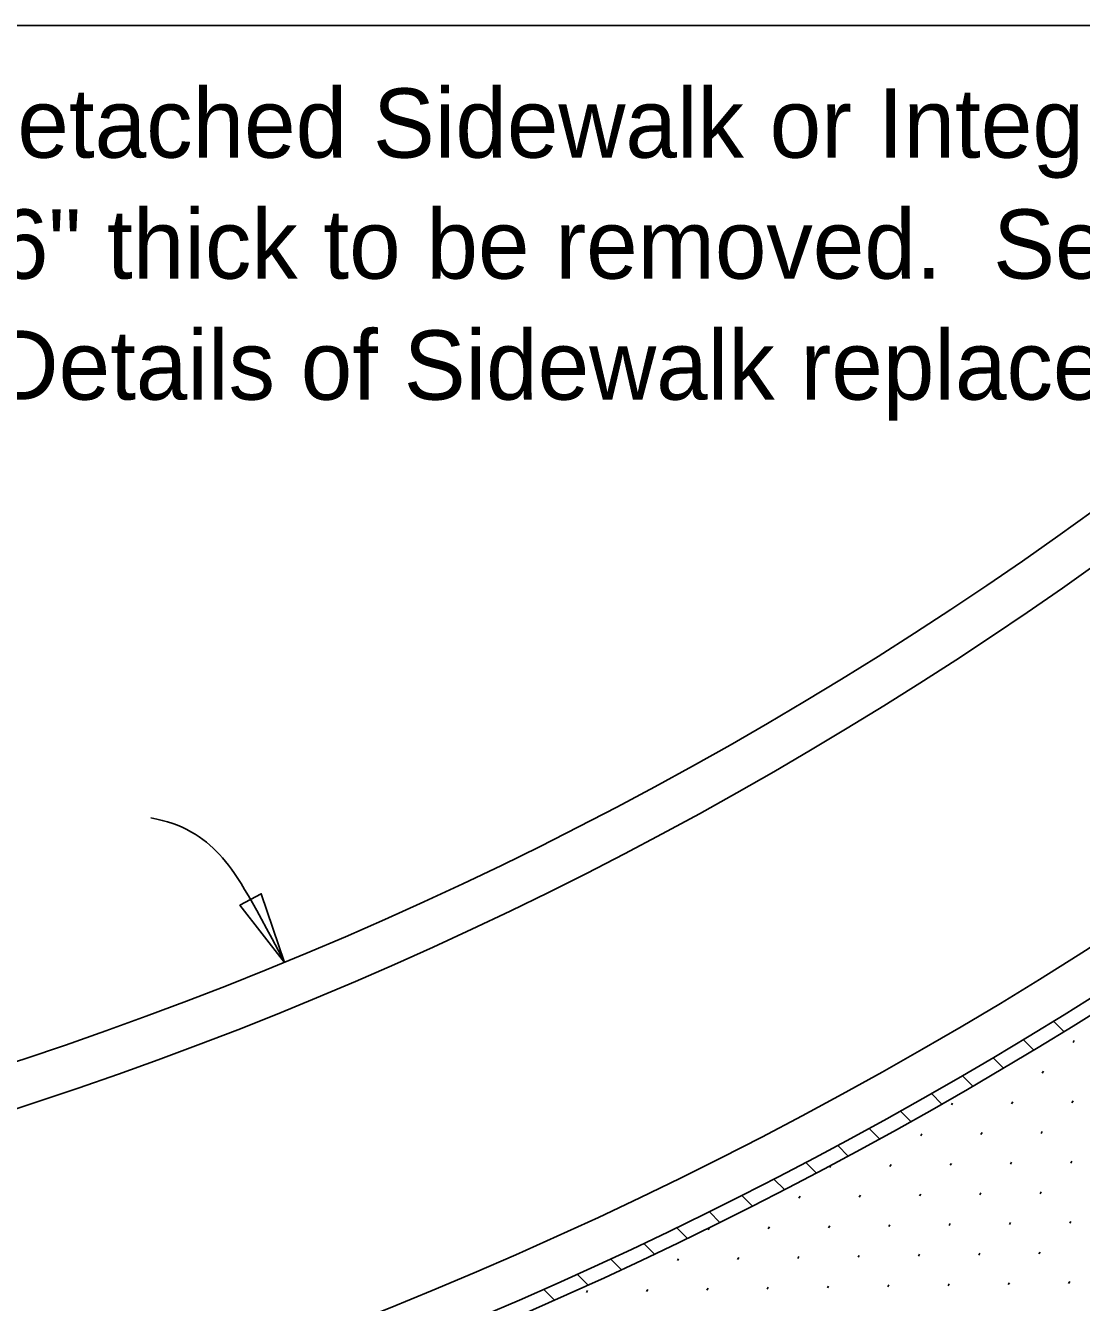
# Model space of a CAD drawing. Extents: x 0 to 41.1, y 0 to 25.9.
# Drawn here: x 31.762 to 34.833, y 22.231 to 25.946 of the extents above; entities that cross this region are included whole.
import ezdxf

# ---------------------------------------------------------------- set-up
doc = ezdxf.new("R2010")
doc.units = 0
for name, color, linetype in [('Dimension', 7, 'Continuous'), ('ExistSuperStruct', 7, 'Continuous'), ('Miscellaneous', 7, 'Continuous'), ('Miscellaneous1', 7, 'Continuous')]:
    doc.layers.add(name, color=color, linetype=linetype)

msp = doc.modelspace()

# ---------------------------------------------------------------- linework, layer by layer
at = {"layer": 'Dimension'}
for points in [[(0, 0), (41.0506, 0), (41.0506, 25.9461), (0, 25.9461)], [(32.5153, 23.2202), (32.4472, 23.4201), (32.3851, 23.3865)]]:
    msp.add_lwpolyline(points, close=True, dxfattribs=at)
msp.add_open_spline([(32.1263, 23.6406), (32.2187, 23.6248), (32.338, 23.5452), (32.4097, 23.4202), (32.5153, 23.2202)], degree=3, dxfattribs=at)
at = {"layer": 'ExistSuperStruct'}
for radius, start, end in [(11.3394, 267.40102, 307.93264), (11.4702, 267.84731, 307.49092), (12.3856, 268.00648, 307.27295), (12.5106, 272.22541, 307.24718), (12.5523, 272.40859, 307.2387)]:
    msp.add_arc((28.1995, 33.7062), radius, start, end, dxfattribs=at)
at = {"layer": 'Miscellaneous'}
for p, q in [((34.7522, 23.0488), (34.7821, 23.0189)), ((34.6643, 22.9953), (34.6945, 22.9651)), ((34.8084, 22.9871), (34.8117, 22.9927)), ((34.5758, 22.9424), (34.6059, 22.9123)), ((34.4867, 22.8901), (34.5169, 22.8599)), ((34.7191, 22.8979), (34.7224, 22.9035)), ((34.3969, 22.8384), (34.4272, 22.8082)), ((34.6299, 22.8086), (34.6331, 22.8142)), ((34.8052, 22.8118), (34.8084, 22.8174)), ((34.3065, 22.7874), (34.3368, 22.7571)), ((34.4546, 22.8054), (34.4578, 22.8109)), ((34.2155, 22.737), (34.246, 22.7065)), ((34.3653, 22.7161), (34.3685, 22.7217)), ((34.5406, 22.7193), (34.5438, 22.7249)), ((34.7159, 22.7226), (34.7191, 22.7282)), ((34.1239, 22.6872), (34.1543, 22.6568)), ((34.0316, 22.6381), (34.0623, 22.6073)), ((34.1007, 22.6236), (34.104, 22.6292)), ((34.276, 22.6268), (34.2793, 22.6324)), ((34.4513, 22.63), (34.4546, 22.6356)), ((34.6266, 22.6333), (34.6299, 22.6389)), ((34.8019, 22.6365), (34.8052, 22.6421)), ((33.9386, 22.5896), (33.9692, 22.5591)), ((34.7127, 22.5473), (34.7159, 22.5529)), ((33.845, 22.5418), (33.876, 22.5108)), ((34.0114, 22.5343), (34.0147, 22.5399)), ((34.1867, 22.5375), (34.19, 22.5431)), ((34.362, 22.5408), (34.3653, 22.5464)), ((34.5374, 22.544), (34.5406, 22.5496)), ((33.7508, 22.4946), (33.7815, 22.4639)), ((33.6559, 22.4481), (33.6869, 22.417)), ((33.7469, 22.4418), (33.7501, 22.4474)), ((33.9222, 22.445), (33.9254, 22.4506)), ((34.0975, 22.4483), (34.1007, 22.4539)), ((34.2728, 22.4515), (34.276, 22.4571)), ((34.4481, 22.4547), (34.4513, 22.4603)), ((34.6234, 22.458), (34.6266, 22.4636)), ((34.7987, 22.4612), (34.8019, 22.4668)), ((33.5603, 22.4023), (33.5912, 22.3714)), ((34.1835, 22.3622), (34.1867, 22.3678)), ((34.3588, 22.3655), (34.362, 22.3711)), ((34.5341, 22.3687), (34.5374, 22.3743)), ((34.7094, 22.372), (34.7127, 22.3776)), ((33.464, 22.3571), (33.4952, 22.326)), ((33.6576, 22.3525), (33.6608, 22.3581)), ((33.8329, 22.3557), (33.8361, 22.3613)), ((34.0082, 22.359), (34.0114, 22.3646)), ((33.3671, 22.3126), (33.3982, 22.2815)), ((33.2694, 22.2689), (33.3007, 22.2376)), ((33.393, 22.26), (33.3963, 22.2656)), ((33.5683, 22.2632), (33.5716, 22.2688)), ((33.7436, 22.2665), (33.7469, 22.2721)), ((33.9189, 22.2697), (33.9222, 22.2753)), ((34.0942, 22.273), (34.0975, 22.2786)), ((34.2695, 22.2762), (34.2728, 22.2818)), ((34.4448, 22.2794), (34.4481, 22.285)), ((34.6201, 22.2827), (34.6234, 22.2883)), ((34.7954, 22.2859), (34.7987, 22.2915))]:
    msp.add_line(p, q, dxfattribs=at)
at = {"layer": 'Miscellaneous1'}
msp.add_lwpolyline([(0, 25.9461), (41.0506, 25.9461), (41.0506, 0), (0, 0)], close=True, dxfattribs=at)

# ---------------------------------------------------------------- texts
at = {"layer": 'Dimension'}
for s, p in [('Existing Detached Sidewalk or Integral Sidewalk ', (30.5244, 25.5616)), ('less than 6" thick to be removed.  See Roadway ', (30.5244, 25.2096)), ('Plans for Details of Sidewalk replacement.', (30.5244, 24.8576))]:
    msp.add_text(s, height=0.2016, dxfattribs=at).set_placement(p)

doc.saveas('drawing.dxf')
